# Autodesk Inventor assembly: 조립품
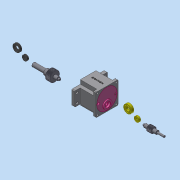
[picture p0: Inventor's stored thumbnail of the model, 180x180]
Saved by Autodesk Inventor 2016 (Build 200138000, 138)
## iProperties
Created: 2020-08
Part Number: 조립품
Material: 일반
Document SubType Name: Assembly
Designer: User
Author: User
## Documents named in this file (10)
- C:\Users\User\Desktop\700815V1003\조립품.iam
- C:\Users\User\Desktop\700815V1003\메인 축.ipt
- C:\Users\User\Desktop\700815V1003\베어링 608.ipt
- C:\Users\User\Desktop\700815V1003\베어링 6003.ipt
- C:\Users\User\Desktop\700815V1003\본체.ipt
- C:\Users\User\Desktop\700815V1003\볼트 M4.ipt
- C:\Users\User\Desktop\700815V1003\서브 축.ipt
- C:\Users\User\Desktop\700815V1003\오일 실 8 22 7.ipt
- C:\Users\User\Desktop\700815V1003\오일 실 17 32 8.ipt
- C:\Users\User\Desktop\700815V1003\커버.ipt
